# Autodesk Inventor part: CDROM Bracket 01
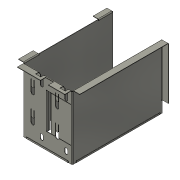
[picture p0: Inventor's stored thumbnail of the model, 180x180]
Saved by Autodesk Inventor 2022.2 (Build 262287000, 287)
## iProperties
Created: 2007-02
Part Number: CDROM Bracket 01
Material: アルミニウム 6061
Document SubType Name: Sheet Metal
Designer: Autodesk, Inc.
Mass: 129.989 g
Surface Area: 981.248 cm^2
Volume: 48.1441 cm^3
Density: 2.7 g/cm^3
Flat Pattern Width: 12.3544 cm
Flat Pattern Length: 41.0638 cm
Flat Pattern Area: 507.318 cm^2
Sheet Metal Rule: Default_mm
Sheet Metal Width: 123.544 mm
Sheet Metal Length: 410.638 mm
Sheet Metal Area: 50731.773 mm^2
Appearance: Silicon Nitride - Polished
Author: Autodesk, Inc.
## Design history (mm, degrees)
node "Contour Flange1"
  sketch "Sketch1"
    geometry: L1 (-77, 41.5)-(77, 41.5); L2 (77, 41.5)-(77, -41.5); L3 (77, -41.5)-(-77, -41.5); L4 (-77, -41.5)-(-77, 41.5); L5 (-77, 41.5)-(77, -41.5); 2 further points
    constraints: 10 end point, 2 parallel, 1 coincident, 1 horizontal, 1 midpoint, 1 perpendicular
    dimensions: "d0" = 154 distance of L1.start L1.end; "d1" = 83 distance of L3.end L1.start
node "Flange1"
node "Flange2"
node "Flange3"
node "Flange4"
node "Flange5"
feature "Corner6" dims "d51" = 3.2 (= CornerReliefSize), "d52" = 0.8 (= BendRadius), "d53" = 0.8 (= Thickness), "d54" = 0, "d165" = 0.8 (= Thickness)
feature "Corner8" dims "d91" = 3.2 (= CornerReliefSize), "d92" = 0.8 (= BendRadius), "d93" = 0.8 (= Thickness), "d94" = 0, "d165" = 0.8 (= Thickness)
sketch "Sketch7"
  geometry: L1 (28, 53.6)-(13, 53.6); L2 (28, 48.2)-(28, 53.6); L3 (13, 48.2)-(28, 48.2); L4 (13, 55.6)-(13, 46.2); L5 (13, 46.2)-(5, 46.2); L6 (5, 46.2)-(5, 55.6); L7 (5, 55.6)-(13, 55.6); L8 (13, 53.6)-(13, 48.2); L9 (0, 81.4)-(10.4, 81.4) reference; L10 (0, 0)-(0, 81.4) reference; 1 further point
  constraints: 16 end point, 4 parallel, 2 perpendicular, 1 midpoint, 1 point on line, 1 vertical alignment, 2 other
  dimensions: "d70" = 8 distance of L6.end L4.start; "d72" = 2 distance between parallel lines of L7 L1; "d73" = 2 distance between parallel lines of L5 L3 (= d72); "d74" = 15 distance of L1.start L1.end; "d76" = 23 distance from line of point (28, 50.9) L6 (derived); "d77" = 9.4 distance of L5.end L6.end; "d78" = 25.8 distance between parallel lines of L9 L7; "d79" = 5 distance between parallel lines of L10 L6
cut "Cut1" sketch "Sketch7" dims "d80" = 0.8 (= Thickness), "d81" = 0
pattern_linear "Rectangular Pattern1" dims "d84" = 42
sketch "Sketch8"
  geometry: L1 (-1.1, 41.9)-(8.9, 41.9); L2 (8.9, 41.9)-(8.9, 27.9); L3 (8.9, 27.9)-(-1.1, 27.9); L4 (-1.1, 27.9)-(-1.1, 41.9); L5 (10.4, 13.6)-(10.4, 46.2) reference; L6 (0, 81.4)-(10.4, 81.4) reference
  constraints: 8 end point, 2 parallel, 1 horizontal, 1 perpendicular
  dimensions: "d85" = 14 distance of L3.end L1.start; "d86" = 10 distance of L1.start L1.end; "d87" = 1.5 distance between parallel lines of L5 L2; "d88" = 39.5 distance between parallel lines of L6 L1
cut "Cut2" sketch "Sketch8" dims "d89" = 0.8 (= Thickness), "d90" = 0
sketch "Sketch9" dims "d95" = 10
  geometry: L1 (0, 81.4)-(0, -0.6); L2 (13, 53.6)-(17.6, 53.6); L3 (17.6, 53.6)-(17.6, 48.2); L4 (17.6, 48.2)-(13, 48.2); L5 (13, 48.2)-(13, 53.6); L6 (28.4, 41.4)-(88.4, 41.4); L7 (88.4, 41.4)-(88.4, 34.4); L8 (88.4, 34.4)-(28.4, 34.4); L9 (28.4, 34.4)-(28.4, 41.4); L10 (28.4, 69.4)-(28.4, 63.4); L11 (93.4, 68.9)-(93.4, 68.9); L12 (82.9, 64.4)-(92.9, 64.4); L13 (92.9, 68.4)-(82.9, 68.4); L14 (82.9, 68.4)-(82.9, 64.4); L15 (92.9, 69.4)-(73.4, 69.4); L16 (73.4, 69.4)-(73.4, 63.4); L17 (73.4, 63.4)-(92.9, 63.4); L18 (37.9, 68.4)-(37.9, 64.4); L19 (28.4, 63.4)-(47.9, 63.4); L20 (47.9, 69.4)-(28.4, 69.4); L21 (47.9, 68.4)-(37.9, 68.4); L22 (37.9, 64.4)-(47.9, 64.4); L23 (48.4, 63.9)-(48.4, 63.9); L24 (48.4, 68.9)-(48.4, 68.9); L25 (93.4, 63.9)-(93.4, 63.9); L26 (108.4, 13.6)-(108.4, 46.2) reference; L27 (108.4, 55.6)-(108.4, 81.4) reference; L28 (0, 81.4)-(108.4, 81.4) reference; A1 r 0.5 centre (92.9, 68.9) between (92.9, 68.4) and (93.4, 68.9); A2 r 0.5 centre (92.9, 68.9) between (93.4, 68.9) and (92.9, 69.4); A3 r 2 centre (82.9, 66.4) between (82.9, 68.4) and (82.9, 64.4); A4 r 2 centre (37.9, 66.4) between (37.9, 68.4) and (37.9, 64.4); A5 r 0.5 centre (47.9, 63.9) between (47.9, 63.4) and (48.4, 63.9); A6 r 0.5 centre (47.9, 63.9) between (48.4, 63.9) and (47.9, 64.4); A7 r 0.5 centre (47.9, 68.9) between (47.9, 68.4) and (48.4, 68.9); A8 r 0.5 centre (47.9, 68.9) between (48.4, 68.9) and (47.9, 69.4); A9 r 0.5 centre (92.9, 63.9) between (93.4, 63.9) and (92.9, 64.4); A10 r 0.5 centre (92.9, 63.9) between (92.9, 63.4) and (93.4, 63.9); 6 further points
  constraints: 50 end point, 20 point on circle, 16 tangent, 12 parallel, 10 centre point, 8 collinear, 7 equal radius, 6 horizontal, 6 midpoint, 6 perpendicular, 6 vertical alignment, 4 point on line, 8 other
  dimensions: "d96" = 13 distance between parallel lines of L1 L5; "d99" = 60 distance of L7.end L8.end; "d100" = 6 distance of point (93.4, 63.4) point (93.4, 69.4); "d102" = 20 distance of L16.end point (93.4, 63.4); "d103" = 7 distance between parallel lines of L8 L6; "d104" = 1 distance between parallel lines of L20 L21; "d105" = 1 distance between parallel lines of L19 L22 (= d104); "d106" = 0.5 radius of A8; "d107" = 10 distance of L18.end L22.end; "d109" = 25 distance from line of L16 L24.end; "d110" = 20 distance between parallel lines of L7 L26; "d111" = 15 distance from line of L27 point (93.4, 69.4); "d112" = 12 distance between parallel lines of L28 L15; "d113" = 40 distance between parallel lines of L28 L6; "d114" = 30.5 distance from line of L28 point (13, 50.9)
cut "Cut3" dims "d115" = 0.8 (= Thickness), "d116" = 0
node "Flange6"
cut "Cut4" dims "d126" = 0.8 (= Thickness), "d127" = 0
pattern_linear "Rectangular Pattern2" dims "d130" = 42
feature "Hem1" dims "d131" = 0.8 (= BendReliefWidth), "d132" = 0.4 (= BendReliefDepth), "d133" = 1.6 (= MinimumRemnant), "d134" = 0.8 (= BendRadius), "d135" = 5, "d136" = 5, "d137" = 3.2 (= 4 x Thickness), "d138" = 0.4 (= 0.5 x Thickness), "d139" = 0.2 (= 0.5 x d138), "d165" = 0.8 (= Thickness), "SeamGap" = 0.01
feature "Hem2" dims "d140" = 0.8 (= BendReliefWidth), "d141" = 0.4 (= BendReliefDepth), "d142" = 1.6 (= MinimumRemnant), "d143" = 0.8 (= BendRadius), "d144" = 3.2 (= 4 x Thickness), "d145" = 0.4 (= 0.5 x Thickness), "d146" = 0.2 (= 0.5 x d145), "d156" = 5, "d157" = 5, "d165" = 0.8 (= Thickness), "SeamGap" = 0.01
feature "Hem3" dims "d147" = 0.8 (= BendReliefWidth), "d148" = 0.4 (= BendReliefDepth), "d149" = 1.6 (= MinimumRemnant), "d150" = 0.8 (= BendRadius), "d151" = 3.2 (= 4 x Thickness), "d152" = 0.4 (= 0.5 x Thickness), "d153" = 0.2 (= 0.5 x d152), "d154" = 5, "d155" = 5, "d165" = 0.8 (= Thickness), "SeamGap" = 0.01
body "Solid1"
face "Plate1" dims "d2" = 0.8 (= BendReliefWidth), "d3" = 0.4 (= BendReliefDepth), "d4" = 1.6 (= MinimumRemnant), "d5" = 0.8 (= BendRadius), "d6" = 110, "d7" = 0.8 (= BendRadius), "d8" = 1, "d9" = 3.2 (= CornerReliefSize), "d10" = 0.8 (= Thickness), "d158" = 0.8 (= JacobiRadiusSize), "d165" = 0.8 (= Thickness), "SeamGap" = 0.01
bend "Bend1" dims "d2" = 0.8 (= BendReliefWidth), "d3" = 0.4 (= BendReliefDepth), "d4" = 1.6 (= MinimumRemnant), "d5" = 0.8 (= BendRadius), "d7" = 0.8 (= BendRadius), "d8" = 1, "d165" = 0.8 (= Thickness), "SeamGap" = 0.01
feature "Corner1" dims "d8" = 1, "d9" = 3.2 (= CornerReliefSize), "d10" = 0.8 (= Thickness), "d158" = 0.8 (= JacobiRadiusSize)
sketch "Sketch2"
  geometry: L1 (-12, 0)-(-12, -81.4); L2 (-12, -81.4)-(0, -81.4); 1 other entity
  constraints: 4 end point, 4 other
face "Plate2" dims "d11" = 0.8 (= BendReliefWidth), "d12" = 0.4 (= BendReliefDepth), "d13" = 1.6 (= MinimumRemnant), "d14" = 0.8 (= BendRadius), "d15" = 12, "d16" = 90 deg, "d17" = 0.8 (= BendRadius), "d18" = 3.2 (= CornerReliefSize), "d19" = 0.8 (= Thickness), "d159" = 0.8 (= JacobiRadiusSize), "d165" = 0.8 (= Thickness), "SeamGap" = 0.01
bend "Bend2" dims "d11" = 0.8 (= BendReliefWidth), "d12" = 0.4 (= BendReliefDepth), "d13" = 1.6 (= MinimumRemnant), "d14" = 0.8 (= BendRadius), "d15" = 12, "d16" = 90 deg, "d17" = 0.8 (= BendRadius), "d165" = 0.8 (= Thickness), "SeamGap" = 0.01
feature "Corner2" dims "d15" = 12, "d16" = 90 deg, "d18" = 3.2 (= CornerReliefSize), "d19" = 0.8 (= Thickness), "d159" = 0.8 (= JacobiRadiusSize)
sketch "Sketch3"
  geometry: L1 (-153.2, -0.8)-(-128.2, -0.8); L2 (-128.2, -0.8)-(-128.2, 10); L3 (-128.2, 10)-(-153.2, 10); L4 (-153.2, 10)-(-153.2, -0.8)
  constraints: 8 end point
face "Plate3" dims "d20" = 0.8 (= BendReliefWidth), "d21" = 0.4 (= BendReliefDepth), "d22" = 1.6 (= MinimumRemnant), "d23" = 0.8 (= BendRadius), "d24" = 25, "d25" = 0, "d26" = 10, "d27" = 90 deg, "d28" = 0.8 (= BendRadius), "d29" = 3.2 (= CornerReliefSize), "d30" = 0.8 (= Thickness), "d160" = 0.8 (= JacobiRadiusSize), "d165" = 0.8 (= Thickness), "SeamGap" = 0.01
bend "Bend3" dims "d20" = 0.8 (= BendReliefWidth), "d21" = 0.4 (= BendReliefDepth), "d22" = 1.6 (= MinimumRemnant), "d23" = 0.8 (= BendRadius), "d26" = 10, "d27" = 90 deg, "d28" = 0.8 (= BendRadius), "d165" = 0.8 (= Thickness), "SeamGap" = 0.01
feature "Corner3" dims "d26" = 10, "d27" = 90 deg, "d29" = 3.2 (= CornerReliefSize), "d30" = 0.8 (= Thickness), "d160" = 0.8 (= JacobiRadiusSize)
sketch "Sketch4"
  geometry: L1 (0, -0.8)-(-25, -0.8); L2 (-25, -0.8)-(-25, 10); L3 (-25, 10)-(0, 10); L4 (0, 10)-(0, -0.8)
  constraints: 8 end point
face "Plate4" dims "d31" = 0.8 (= BendReliefWidth), "d32" = 0.4 (= BendReliefDepth), "d33" = 1.6 (= MinimumRemnant), "d34" = 0.8 (= BendRadius), "d35" = 25, "d36" = 0, "d37" = 10, "d38" = 90 deg, "d39" = 0.8 (= BendRadius), "d40" = 3.2 (= CornerReliefSize), "d41" = 0.8 (= Thickness), "d161" = 0.8 (= JacobiRadiusSize), "d165" = 0.8 (= Thickness), "SeamGap" = 0.01
bend "Bend4" dims "d31" = 0.8 (= BendReliefWidth), "d32" = 0.4 (= BendReliefDepth), "d33" = 1.6 (= MinimumRemnant), "d34" = 0.8 (= BendRadius), "d37" = 10, "d38" = 90 deg, "d39" = 0.8 (= BendRadius), "d165" = 0.8 (= Thickness), "SeamGap" = 0.01
feature "Corner4" dims "d37" = 10, "d38" = 90 deg, "d40" = 3.2 (= CornerReliefSize), "d41" = 0.8 (= Thickness), "d161" = 0.8 (= JacobiRadiusSize)
sketch "Sketch5"
  geometry: L1 (10, 0)-(10, 108.4); L2 (10, 108.4)-(0, 108.4); 1 other entity
  constraints: 4 end point, 4 other
face "Plate5" dims "d42" = 0.8 (= BendReliefWidth), "d43" = 0.4 (= BendReliefDepth), "d44" = 1.6 (= MinimumRemnant), "d45" = 0.8 (= BendRadius), "d46" = 10, "d47" = 90 deg, "d48" = 0.8 (= BendRadius), "d49" = 3.2 (= CornerReliefSize), "d50" = 0.8 (= Thickness), "d162" = 0.8 (= JacobiRadiusSize), "d165" = 0.8 (= Thickness), "SeamGap" = 0.01
bend "Bend5" dims "d42" = 0.8 (= BendReliefWidth), "d43" = 0.4 (= BendReliefDepth), "d44" = 1.6 (= MinimumRemnant), "d45" = 0.8 (= BendRadius), "d46" = 10, "d47" = 90 deg, "d48" = 0.8 (= BendRadius), "d165" = 0.8 (= Thickness), "SeamGap" = 0.01
feature "Corner5" dims "d46" = 10, "d47" = 90 deg, "d49" = 3.2 (= CornerReliefSize), "d50" = 0.8 (= Thickness), "d162" = 0.8 (= JacobiRadiusSize)
sketch "Sketch6"
  geometry: L1 (0, -88.4)-(-12, -88.4); L2 (-12, -88.4)-(-12, 0); 1 other entity
  constraints: 4 end point, 4 other
face "Plate6" dims "d55" = 0.8 (= BendReliefWidth), "d56" = 0.4 (= BendReliefDepth), "d57" = 1.6 (= MinimumRemnant), "d58" = 0.8 (= BendRadius), "d61" = 12, "d62" = 90 deg, "d63" = 0.8 (= BendRadius), "d64" = 3.2 (= CornerReliefSize), "d65" = 0.8 (= Thickness), "d66" = 0, "d67" = 20, "d163" = 0.8 (= JacobiRadiusSize), "d165" = 0.8 (= Thickness), "SeamGap" = 0.01
bend "Bend6" dims "d55" = 0.8 (= BendReliefWidth), "d56" = 0.4 (= BendReliefDepth), "d57" = 1.6 (= MinimumRemnant), "d58" = 0.8 (= BendRadius), "d61" = 12, "d62" = 90 deg, "d63" = 0.8 (= BendRadius), "d165" = 0.8 (= Thickness), "SeamGap" = 0.01
feature "Corner7" dims "d61" = 12, "d62" = 90 deg, "d64" = 3.2 (= CornerReliefSize), "d65" = 0.8 (= Thickness), "d163" = 0.8 (= JacobiRadiusSize)
sketch "Sketch10"
  geometry: L1 (0, -59.99)-(0, -0.01); L2 (0, -0.01)-(-5, -0.01); L3 (-5, -0.01)-(-5, -59.99); L4 (-5, -59.99)-(0, -59.99)
  constraints: 8 end point
face "Plate7" dims "d117" = 0.8 (= BendReliefWidth), "d118" = 0.4 (= BendReliefDepth), "d119" = 1.6 (= MinimumRemnant), "d120" = 0.8 (= BendRadius), "d121" = 5, "d122" = 90 deg, "d123" = 0.8 (= BendRadius), "d124" = 3.2 (= CornerReliefSize), "d125" = 0.8 (= Thickness), "d164" = 0.8 (= JacobiRadiusSize), "d165" = 0.8 (= Thickness), "SeamGap" = 0.01
bend "Bend7" dims "d117" = 0.8 (= BendReliefWidth), "d118" = 0.4 (= BendReliefDepth), "d119" = 1.6 (= MinimumRemnant), "d120" = 0.8 (= BendRadius), "d121" = 5, "d122" = 90 deg, "d123" = 0.8 (= BendRadius), "d165" = 0.8 (= Thickness), "SeamGap" = 0.01
feature "Corner9" dims "d121" = 5, "d122" = 90 deg, "d124" = 3.2 (= CornerReliefSize), "d125" = 0.8 (= Thickness), "d164" = 0.8 (= JacobiRadiusSize)
sketch "Sketch11"
  geometry: L1 (-0.8, 0)-(0, 0); L2 (0.4, 0)-(0.4, 2.2); L3 (0.4, 2.2)-(1.2, 2.2); L4 (1.2, 2.2)-(1.2, 0); A1 r 0.2 centre (0.2, 0) between (0, 0) and (0.4, 0); A2 r 1 centre (0.2, 0) between (-0.8, 0) and (1.2, 0)
  constraints: 8 end point, 4 point on circle
sketch "Sketch12"
  geometry: L1 (-0.8, 0)-(0, 0); L2 (0.4, 0)-(0.4, 2.2); L3 (0.4, 2.2)-(1.2, 2.2); L4 (1.2, 2.2)-(1.2, 0); A1 r 0.2 centre (0.2, 0) between (0, 0) and (0.4, 0); A2 r 1 centre (0.2, 0) between (-0.8, 0) and (1.2, 0); 2 further points
  constraints: 8 end point, 4 point on circle
sketch "Sketch13"
  geometry: L1 (-0.8, 0)-(0, 0); L2 (0.4, 0)-(0.4, 2.2); L3 (0.4, 2.2)-(1.2, 2.2); L4 (1.2, 2.2)-(1.2, 0); A1 r 0.2 centre (0.2, 0) between (0, 0) and (0.4, 0); A2 r 1 centre (0.2, 0) between (-0.8, 0) and (1.2, 0); 2 further points
  constraints: 8 end point, 4 point on circle
feature "Definition1" dims "d0" = 0.8 (derived)
other parameters: "Thickness" = 0.8 (derived), "BendRadius" = 0.8 (= Thickness), "BendReliefWidth" = 0.8 (= Thickness), "BendReliefDepth" = 0.4 (= 0.5 x Thickness), "CornerReliefSize" = 3.2 (= 4 x Thickness), "MinimumRemnant" = 1.6 (= 2 x Thickness), "TransitionRadius" = 0.8 (= BendRadius), "JacobiRadiusSize" = 0.8 (= BendRadius), "GapSize" = 0.8 (= Thickness), "BendRadius" = 0.8, "BendReliefDepth" = 0.4, "BendReliefWidth" = 0.8, "CornerReliefSize" = 3.2, "JacobiRadiusSize" = 0.8, "MinimumRemnant" = 1.6, "Thickness" = 0.8, "TransitionRadius" = 0.8, "GapSize" = 0.8, "d1" = 0
